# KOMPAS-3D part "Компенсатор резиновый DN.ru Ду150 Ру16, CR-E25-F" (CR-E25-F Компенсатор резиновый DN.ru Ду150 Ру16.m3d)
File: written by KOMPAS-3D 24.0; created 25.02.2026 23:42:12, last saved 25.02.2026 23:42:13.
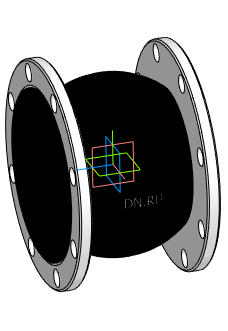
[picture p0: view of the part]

Document properties: Автор: DN.RU; Полное имя файла: D:\PROJECT CAD\DN.RU\...178(4)(ACTUALE). CR-E25-F Компенсатор резиновый DN.ru Ру10-16\DN150_PN16\CR-E25-F Компенсатор резиновый DN.ru Ду150 Ру16.m3d

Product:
- Body: Твердое тело2  | qty 1
    Масса: 25.350854
- Part/product: Компенсатор резиновый DN.ru Ду150 Ру16  | designation CR-E25-F
    Масса: 13.13
    Раздел спецификации: Прочие изделия
    Комментарий: D140-02178
    Примечание: D140-02178
    additional columns: Типовые

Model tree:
1. Твердое тело2  (labels: Твердое тело2)

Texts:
  CR-E25-F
